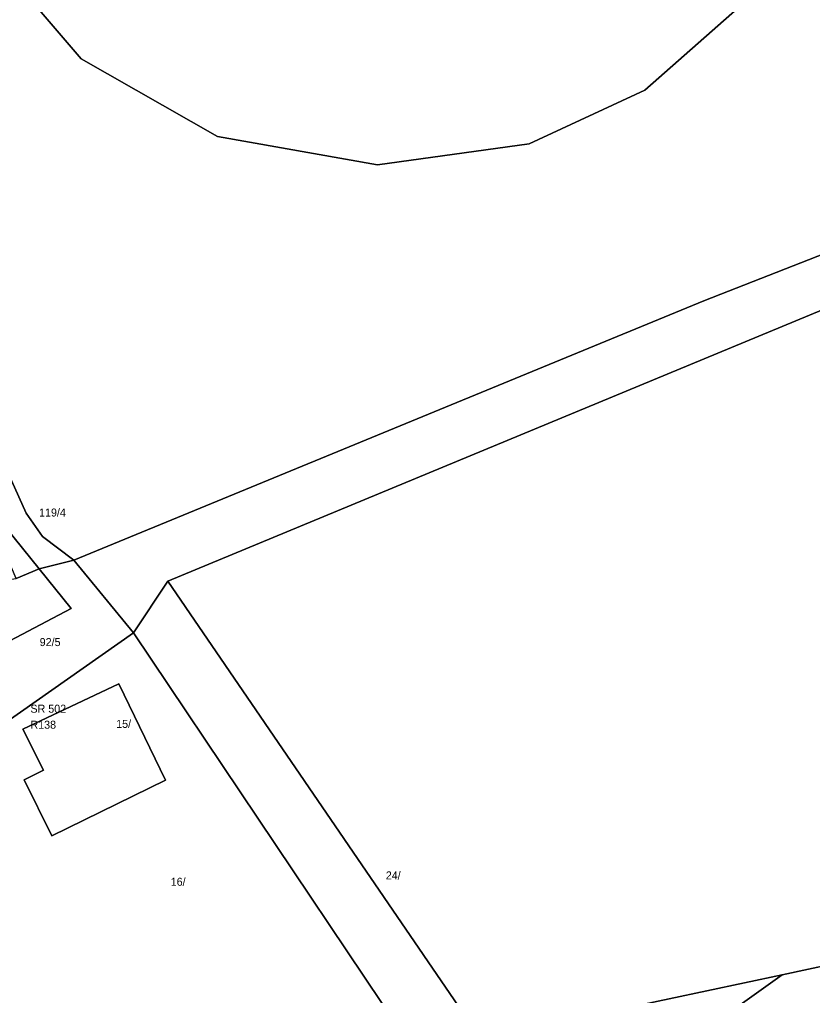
# Model space of a CAD drawing. Extents: x -793400 to -756198, y -1074141 to -1042963.
# Drawn here: x -783321.3 to -783247, y -1065140.1 to -1065048.6 of the extents above; entities that cross this region are included whole.
import ezdxf

# ---------------------------------------------------------------- set-up
doc = ezdxf.new("R2010")
doc.units = 0
for name, color, linetype in [('Parcela', 7, 'Continuous'), ('Popiskový text - Parcela', 7, 'Continuous'), ('Popiskový text - Rozpojovací skříň nn - SJZ', 7, 'Continuous'), ('Popiskový text - Rozpojovací skříň nn - Typ', 7, 'Continuous'), ('Stavební objekt', 7, 'Continuous')]:
    doc.layers.add(name, color=color, linetype=linetype)

msp = doc.modelspace()

# ---------------------------------------------------------------- linework, layer by layer
at = {"layer": 'Parcela'}
for points in [[(-783243.73, -1064923.28), (-783248.06, -1065037.91), (-783252.67, -1065046.4), (-783262.68, -1065055.25), (-783273.51, -1065060.26), (-783287.72, -1065062.23), (-783302.71, -1065059.57), (-783315.49, -1065052.3), (-783324.71, -1065041.56), (-783328.14, -1065033.82), (-783330.68, -1065033.82), (-783329.69, -1065008.77), (-783328.34, -1064974.7), (-783328.17, -1064970.39), (-783326.14, -1064918.86), (-783322.67, -1064918.07), (-783317.37, -1064912.36), (-783311.76, -1064907), (-783304.84, -1064902.58), (-783289.73, -1064897.8), (-783276.94, -1064897.48), (-783263.64, -1064902.09), (-783250.99, -1064911.02)], [(-783307.38, -1065101.23), (-783310.58, -1065106.07), (-783316.18, -1065099.27), (-783257.14, -1065074.97), (-783168.98, -1065040.4), (-783145.36, -1065032.08), (-783114.42, -1065022.83), (-783104.18, -1065020.25), (-783097.92, -1065018.68), (-783096.69, -1065018.37), (-783093.58, -1065021.26), (-783113.22, -1065027.75), (-783237.38, -1065072.22)], [(-783316.18, -1065099.27), (-783319.43, -1065100.1), (-783324.82, -1065093.48), (-783326.02, -1065090.69), (-783337.41, -1065064.91), (-783328.65, -1065077.12), (-783320.65, -1065094.88), (-783319.12, -1065097.06)], [(-783319.43, -1065100.1), (-783321.58, -1065100.98), (-783324.82, -1065093.48)], [(-783324.47, -1065115.8), (-783325.71, -1065116.67), (-783333.19, -1065112.61), (-783316.42, -1065103.79), (-783319.43, -1065100.1), (-783316.18, -1065099.27), (-783310.58, -1065106.07)], [(-783267.78, -1065160.5), (-783272.44, -1065162), (-783275.15, -1065156.9), (-783287.28, -1065140.81), (-783310.58, -1065106.07), (-783307.38, -1065101.23), (-783278.06, -1065144.14), (-783272.83, -1065150.26)], [(-783330.54, -1065148.15), (-783331.93, -1065148.39), (-783328.95, -1065129.54), (-783325.71, -1065116.67), (-783324.47, -1065115.8), (-783310.58, -1065106.07), (-783287.28, -1065140.81), (-783302.94, -1065143.6), (-783306.79, -1065144.23)], [(-783307.59, -1065119.89), (-783311.98, -1065110.86), (-783320.97, -1065115.1), (-783319.03, -1065118.96), (-783320.85, -1065119.87), (-783318.24, -1065125.1)], [(-783307.59, -1065119.89), (-783318.24, -1065125.1), (-783320.85, -1065119.87), (-783319.03, -1065118.96), (-783320.97, -1065115.1), (-783311.98, -1065110.86)], [(-783238.19, -1065151), (-783251.45, -1065155.25), (-783256.08, -1065152.5), (-783257.6, -1065146.24), (-783258.13, -1065144.05), (-783249.82, -1065138.12), (-783242.83, -1065136.63), (-783239.65, -1065146.32)], [(-783271.73, -1065149.79), (-783272.83, -1065150.26), (-783278.06, -1065144.14), (-783249.82, -1065138.12), (-783258.13, -1065144.05)]]:
    msp.add_lwpolyline(points, close=True, dxfattribs=at)
for points in [[(-783168.98, -1065040.4), (-783257.14, -1065074.97), (-783316.18, -1065099.27), (-783319.12, -1065097.06), (-783320.65, -1065094.88), (-783328.65, -1065077.12), (-783330.34, -1065073.38), (-783335.81, -1065059.64), (-783336.25, -1065053.85), (-783341.44, -1065052.54), (-783340.71, -1065048.53)], [(-783324.71, -1065041.56), (-783315.49, -1065052.3), (-783302.71, -1065059.57), (-783287.72, -1065062.23), (-783273.51, -1065060.26), (-783262.68, -1065055.25), (-783252.67, -1065046.4)], [(-783242.83, -1065136.63), (-783249.82, -1065138.12), (-783278.06, -1065144.14), (-783307.38, -1065101.23), (-783237.38, -1065072.22)], [(-783424.51, -1065149.24), (-783423.77, -1065139.97), (-783418.93, -1065135.05), (-783416.29, -1065132.81), (-783411.41, -1065130.62), (-783392.8, -1065125.31), (-783373.16, -1065118.84), (-783331.63, -1065102.5), (-783321.58, -1065100.98), (-783319.43, -1065100.1), (-783316.42, -1065103.79), (-783333.19, -1065112.61), (-783336.58, -1065111.89), (-783359.09, -1065121.02), (-783370.11, -1065125.47), (-783383.74, -1065131.01), (-783410.44, -1065138.09), (-783413.48, -1065139.98), (-783415.63, -1065142.9)]]:
    msp.add_lwpolyline(points, dxfattribs=at)
at = {"layer": 'Stavební objekt'}
msp.add_lwpolyline([(-783307.59, -1065119.89), (-783318.24, -1065125.1), (-783320.85, -1065119.87), (-783319.03, -1065118.96), (-783320.97, -1065115.1), (-783311.98, -1065110.86)], close=True, dxfattribs=at)

# ---------------------------------------------------------------- texts
at = {"layer": 'Popiskový text - Parcela'}
for s, p in [('119/4', (-783319.443, -1065095.187)), ('92/5', (-783319.385, -1065107.327)), ('15/', (-783312.218, -1065114.991)), ('24/', (-783286.949, -1065129.188)), ('16/', (-783307.105, -1065129.785))]:
    msp.add_text(s, height=0.75, dxfattribs=at).set_placement(p)
at = {"layer": 'Popiskový text - Rozpojovací skříň nn - SJZ'}
msp.add_text('R138', height=0.75, dxfattribs=at).set_placement((-783320.25, -1065115.07))
at = {"layer": 'Popiskový text - Rozpojovací skříň nn - Typ'}
msp.add_text('SR 502', height=0.75, dxfattribs=at).set_placement((-783320.25, -1065113.57))

doc.saveas('drawing.dxf')
